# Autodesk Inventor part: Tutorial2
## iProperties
Shininess: 64.0
Length Units: 11269
Angle Units: 11279
Time Units: 11290
Mass Units: 11283
Length Display Precision: 3
Angle Display Precision: 2
Compacted: True
Part Number: Tutorial2
Document SubType Name: Modeling
Created: 2002-12
Designer: deepak
Density: 0.0
Volumn: 0.0
Area: 0.0
PropertySet Name: Model Information
Control State: 0
Master: False
Checked Out: False
Author: deepak
